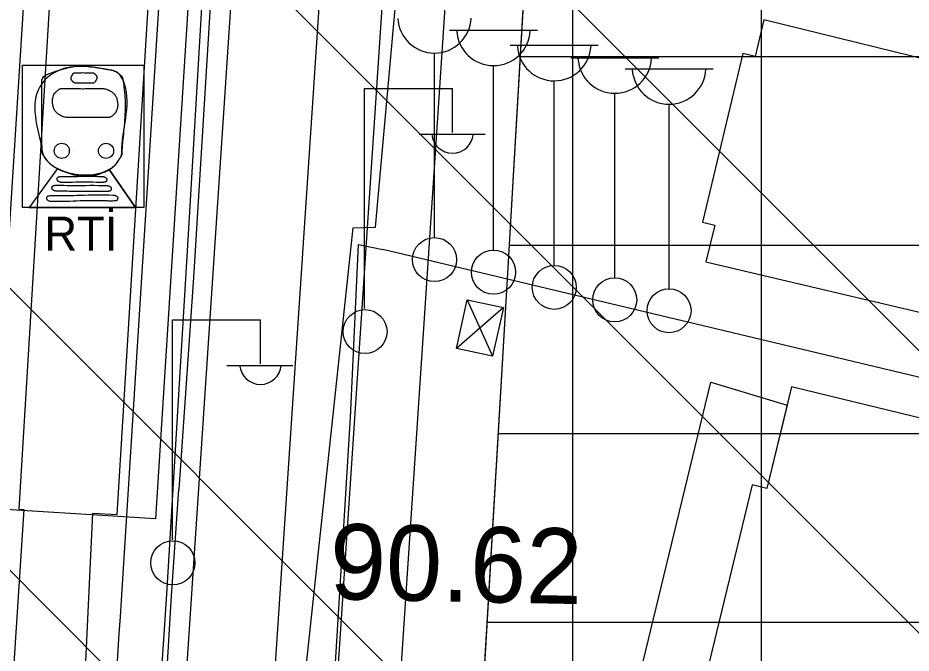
# Model space of a CAD drawing. Extents: x 417995 to 421451, y 4454518 to 4458015.
# Drawn here: x 420306.6 to 420377.6, y 4456593.7 to 4456644.2 of the extents above; entities that cross this region are included whole.
import ezdxf

# ---------------------------------------------------------------- set-up
doc = ezdxf.new("R2010")
doc.units = 0
for name, color, linetype in [('ADAKENARI', 7, 'Continuous'), ('B_Imalat', 7, 'Continuous'), ('B_Ins_Halinde', 7, 'Continuous'), ('B_Sundurma', 7, 'Continuous'), ('KALDIRIM_FAT', 7, 'Continuous'), ('LJ_SEMBOL', 7, 'Continuous'), ('PL_RAY_ISTASYON', 7, 'Continuous'), ('PL_RAYLI_TOPLU_TAŞIMA_İST', 7, 'Continuous'), ('PL_TİCARET', 7, 'Continuous'), ('RAYLI_TOPLU_TAŞIMA_HATTI', 7, 'Continuous'), ('S_Cad_Sok_Lambasi', 7, 'Continuous'), ('S_Elektrik_Diregi', 7, 'Continuous'), ('Sinir_Duvar_tek_tarafa_ait', 7, 'Continuous'), ('Sinir_Ist_Duvari', 7, 'Continuous'), ('SN_TR_SIVILASMA', 7, 'Continuous'), ('TRFAT_TİCARET', 7, 'Continuous'), ('Y_Kot_Noktasi', 7, 'Continuous'), ('Yol_Sose', 7, 'Continuous')]:
    doc.layers.add(name, color=color, linetype=linetype)

msp = doc.modelspace()

# ---------------------------------------------------------------- linework, layer by layer
at = {"layer": 'ADAKENARI'}
for p, q in [((420345.548, 4456624.341), (420347.312, 4456654.323)), ((420342.628, 4456574.693), (420345.548, 4456624.341))]:
    msp.add_line(p, q, dxfattribs=at)
at = {"layer": 'B_Imalat'}
msp.add_lwpolyline([(420388.142, 4456638.59), (420365.892, 4456644.052), (420365.209, 4456641.131), (420364.22, 4456641.368), (420361.019, 4456627.951), (420361.992, 4456627.718), (420361.292, 4456624.801), (420383.352, 4456619.614), (420384.566, 4456624.442), (420384.724, 4456624.389), (420386.982, 4456633.686)], close=True, dxfattribs=at)
at = {"layer": 'B_Ins_Halinde'}
for points in [[(420318.123, 4456664.608), (420315.622, 4456664.738), (420315.747, 4456667.522), (420312.826, 4456667.633), (420312.72, 4456665.065), (420310.259, 4456665.167), (420306.623, 4456605.135), (420307.028, 4456605.1), (420305.849, 4456587.154), (420311.662, 4456586.825), (420312.516, 4456604.804), (420314.463, 4456604.712)], [(420398.93, 4456606.339), (420403.896, 4456605.028), (420395.231, 4456569.269), (420352.988, 4456579.324), (420361.683, 4456615.244), (420367.747, 4456613.415), (420366.134, 4456606.778), (420364.969, 4456607.061), (420361.326, 4456592.074), (420386.941, 4456585.848), (420387.211, 4456586.956), (420392.806, 4456585.596), (420394.723, 4456593.481), (420395.745, 4456593.233)], [(420368.1, 4456614.868), (420366.134, 4456606.778), (420364.969, 4456607.061), (420361.326, 4456592.074), (420386.941, 4456585.848), (420387.211, 4456586.956), (420392.806, 4456585.596), (420394.723, 4456593.481), (420395.745, 4456593.233), (420399.168, 4456607.316)]]:
    msp.add_lwpolyline(points, close=True, dxfattribs=at)
at = {"layer": 'B_Sundurma'}
for p, q in [((420345.194, 4456621.18), (420341.454, 4456617.91)), ((420342.284, 4456621.79), (420344.324, 4456617.29))]:
    msp.add_line(p, q, dxfattribs=at)
msp.add_lwpolyline([(420341.454, 4456617.91), (420342.284, 4456621.79), (420345.194, 4456621.18), (420344.324, 4456617.29)], close=True, dxfattribs=at)
at = {"layer": 'KALDIRIM_FAT'}
for p, q in [((420370.124, 4457345.917), (420299.038, 4456277.891)), ((420377.108, 4457345.448), (420312.526, 4456375.14)), ((420348.426, 4456763.935), (420332.307, 4456521.76)), ((420342.794, 4456754.609), (420327.461, 4456524.245))]:
    msp.add_line(p, q, dxfattribs=at)
at = {"layer": 'LJ_SEMBOL'}
for p, q in [((420309.699, 4456632.214), (420307.452, 4456629.116)), ((420309.699, 4456632.214), (420307.452, 4456629.116)), ((420313.826, 4456632.14), (420315.912, 4456629.116)), ((420315.912, 4456629.116), (420313.826, 4456632.14)), ((420307.452, 4456629.116), (420315.912, 4456629.116))]:
    msp.add_line(p, q, dxfattribs=at)
msp.add_lwpolyline([(420306.911, 4456640.439), (420316.564, 4456640.439), (420316.564, 4456629.116), (420306.911, 4456629.116)], close=True, dxfattribs=at)
for centre in [(420310.047, 4456633.628), (420310.047, 4456633.628), (420313.569, 4456633.628), (420313.569, 4456633.628)]:
    msp.add_circle(centre, 0.601, dxfattribs=at)
for points in [[(420308.45, 4456634.013), (420308.45, 4456638.969), (420309.853, 4456640.044), (420313.523, 4456640.133), (420314.597, 4456639.745), (420314.925, 4456639.238), (420314.836, 4456633.804), (420314.733, 4456633.142), (420314.616, 4456632.963), (420314.448, 4456632.699), (420313.702, 4456632.072), (420310.002, 4456632.072), (420309.226, 4456632.52), (420308.778, 4456632.968), (420308.469, 4456633.699), (420308.45, 4456634.013)], [(420311.938, 4456639.015), (420311.133, 4456639.018), (420311.109, 4456639.02), (420311.086, 4456639.024), (420311.042, 4456639.04), (420311.02, 4456639.052), (420310.999, 4456639.065), (420310.979, 4456639.079), (420310.96, 4456639.095), (420310.941, 4456639.113), (420310.923, 4456639.132), (420310.889, 4456639.171), (420310.857, 4456639.214), (420310.826, 4456639.257), (420310.808, 4456639.29), (420310.796, 4456639.326), (420310.788, 4456639.401), (420310.789, 4456639.42), (420310.792, 4456639.439), (420310.799, 4456639.476), (420310.811, 4456639.513), (420310.826, 4456639.547), (420310.849, 4456639.593), (420310.873, 4456639.642), (420310.899, 4456639.69), (420310.914, 4456639.713), (420310.928, 4456639.736), (420310.943, 4456639.756), (420310.959, 4456639.775), (420310.977, 4456639.792), (420310.996, 4456639.808), (420311.016, 4456639.82), (420311.037, 4456639.829), (420311.059, 4456639.835), (420311.082, 4456639.837), (420311.491, 4456639.837), (420311.681, 4456639.845)], [(420310.803, 4456639.301), (420310.796, 4456639.326), (420310.792, 4456639.345), (420310.789, 4456639.363), (420310.788, 4456639.401), (420310.789, 4456639.42), (420310.792, 4456639.439), (420310.799, 4456639.476), (420310.811, 4456639.513), (420310.826, 4456639.547), (420310.849, 4456639.593), (420310.873, 4456639.642), (420310.899, 4456639.69), (420310.914, 4456639.713), (420310.928, 4456639.736), (420310.943, 4456639.756), (420310.959, 4456639.775), (420310.977, 4456639.792), (420310.996, 4456639.808), (420311.016, 4456639.82), (420311.037, 4456639.829), (420311.059, 4456639.835), (420311.082, 4456639.837), (420311.184, 4456639.837), (420311.287, 4456639.836), (420311.389, 4456639.835), (420311.491, 4456639.837), (420311.681, 4456639.845)], [(420311.681, 4456639.845), (420312.496, 4456639.834), (420312.52, 4456639.833), (420312.543, 4456639.828), (420312.587, 4456639.812), (420312.609, 4456639.801), (420312.63, 4456639.788), (420312.65, 4456639.773), (420312.669, 4456639.757), (420312.688, 4456639.739), (420312.706, 4456639.72), (420312.74, 4456639.681), (420312.772, 4456639.639), (420312.803, 4456639.595), (420312.821, 4456639.562), (420312.833, 4456639.526), (420312.841, 4456639.451), (420312.84, 4456639.432), (420312.837, 4456639.414), (420312.83, 4456639.376), (420312.818, 4456639.34), (420312.803, 4456639.305), (420312.78, 4456639.259), (420312.756, 4456639.21), (420312.729, 4456639.163), (420312.715, 4456639.139), (420312.701, 4456639.116), (420312.686, 4456639.096), (420312.67, 4456639.077), (420312.652, 4456639.06), (420312.633, 4456639.044), (420312.613, 4456639.032), (420312.592, 4456639.023), (420312.57, 4456639.017), (420312.547, 4456639.015), (420312.138, 4456639.015), (420311.938, 4456639.015)], [(420311.681, 4456639.845), (420312.496, 4456639.834), (420312.52, 4456639.833), (420312.543, 4456639.828), (420312.587, 4456639.812), (420312.609, 4456639.801), (420312.63, 4456639.788), (420312.65, 4456639.773), (420312.669, 4456639.757), (420312.688, 4456639.739), (420312.706, 4456639.72), (420312.74, 4456639.681), (420312.772, 4456639.639), (420312.803, 4456639.595), (420312.821, 4456639.562), (420312.826, 4456639.551)], [(420311.938, 4456639.015), (420311.133, 4456639.018), (420311.109, 4456639.02), (420311.086, 4456639.024), (420311.042, 4456639.04), (420311.02, 4456639.052), (420310.999, 4456639.065), (420310.979, 4456639.079), (420310.96, 4456639.095), (420310.941, 4456639.113), (420310.923, 4456639.132), (420310.889, 4456639.171), (420310.857, 4456639.214), (420310.826, 4456639.257), (420310.808, 4456639.29), (420310.803, 4456639.301)], [(420312.826, 4456639.551), (420312.833, 4456639.526), (420312.837, 4456639.508), (420312.84, 4456639.489), (420312.841, 4456639.451), (420312.84, 4456639.432), (420312.837, 4456639.414), (420312.83, 4456639.376), (420312.818, 4456639.34), (420312.803, 4456639.305), (420312.78, 4456639.259), (420312.756, 4456639.21), (420312.729, 4456639.163), (420312.715, 4456639.139), (420312.701, 4456639.116), (420312.686, 4456639.096), (420312.67, 4456639.077), (420312.652, 4456639.06), (420312.633, 4456639.044), (420312.613, 4456639.032), (420312.592, 4456639.023), (420312.57, 4456639.017), (420312.547, 4456639.015), (420312.138, 4456639.015), (420311.938, 4456639.015)], [(420311.796, 4456636.287), (420310.482, 4456636.285), (420310.383, 4456636.292), (420310.286, 4456636.309), (420310.097, 4456636.37), (420309.915, 4456636.461), (420309.825, 4456636.516), (420309.737, 4456636.575), (420309.646, 4456636.651), (420309.565, 4456636.738), (420309.495, 4456636.837), (420309.465, 4456636.889), (420309.436, 4456636.945), (420309.387, 4456637.065), (420309.35, 4456637.187), (420309.325, 4456637.31), (420309.309, 4456637.434), (420309.303, 4456637.558), (420309.308, 4456637.684), (420309.327, 4456637.809), (420309.361, 4456637.933), (420309.428, 4456638.098), (420309.52, 4456638.248), (420309.557, 4456638.291), (420309.597, 4456638.332), (420309.647, 4456638.379), (420309.698, 4456638.424), (420309.753, 4456638.466), (420309.811, 4456638.506), (420309.93, 4456638.565), (420310.057, 4456638.589), (420310.29, 4456638.591), (420310.522, 4456638.59), (420310.987, 4456638.582), (420311.452, 4456638.574), (420311.685, 4456638.572), (420311.917, 4456638.573), (420312.006, 4456638.576)], [(420309.303, 4456637.607), (420309.308, 4456637.684), (420309.327, 4456637.809), (420309.361, 4456637.933), (420309.428, 4456638.098), (420309.52, 4456638.248), (420309.557, 4456638.291), (420309.597, 4456638.332), (420309.647, 4456638.379), (420309.698, 4456638.424), (420309.753, 4456638.466), (420309.811, 4456638.506), (420309.868, 4456638.539), (420309.899, 4456638.553), (420309.93, 4456638.565), (420309.993, 4456638.582), (420310.057, 4456638.589), (420310.29, 4456638.591), (420310.522, 4456638.59), (420310.987, 4456638.582), (420311.452, 4456638.574), (420311.685, 4456638.572), (420311.917, 4456638.573), (420312.006, 4456638.576)], [(420312.006, 4456638.576), (420313.319, 4456638.577), (420313.418, 4456638.57), (420313.515, 4456638.553), (420313.704, 4456638.492), (420313.887, 4456638.401), (420313.976, 4456638.347), (420314.064, 4456638.287), (420314.156, 4456638.212), (420314.236, 4456638.124), (420314.306, 4456638.026), (420314.337, 4456637.973), (420314.365, 4456637.918), (420314.415, 4456637.797), (420314.451, 4456637.675), (420314.477, 4456637.552), (420314.493, 4456637.429), (420314.499, 4456637.304), (420314.493, 4456637.179), (420314.475, 4456637.053), (420314.441, 4456636.929), (420314.374, 4456636.765), (420314.281, 4456636.615), (420314.244, 4456636.571), (420314.205, 4456636.53), (420314.155, 4456636.483), (420314.103, 4456636.439), (420314.049, 4456636.396), (420313.991, 4456636.357), (420313.871, 4456636.298), (420313.744, 4456636.274), (420313.512, 4456636.271), (420313.279, 4456636.272), (420312.814, 4456636.28), (420312.349, 4456636.289), (420312.117, 4456636.29), (420311.884, 4456636.289), (420311.796, 4456636.287)], [(420312.006, 4456638.576), (420313.319, 4456638.577), (420313.418, 4456638.57), (420313.515, 4456638.553), (420313.704, 4456638.492), (420313.751, 4456638.471), (420313.797, 4456638.449), (420313.887, 4456638.401), (420313.976, 4456638.347), (420314.064, 4456638.287), (420314.156, 4456638.212), (420314.236, 4456638.124), (420314.306, 4456638.026), (420314.337, 4456637.973), (420314.365, 4456637.918), (420314.415, 4456637.797), (420314.451, 4456637.675), (420314.477, 4456637.552), (420314.493, 4456637.429), (420314.499, 4456637.304), (420314.498, 4456637.255)], [(420311.796, 4456636.287), (420310.482, 4456636.285), (420310.383, 4456636.292), (420310.286, 4456636.309), (420310.097, 4456636.37), (420310.05, 4456636.391), (420310.004, 4456636.413), (420309.915, 4456636.461), (420309.825, 4456636.516), (420309.737, 4456636.575), (420309.646, 4456636.651), (420309.565, 4456636.738), (420309.495, 4456636.837), (420309.465, 4456636.889), (420309.436, 4456636.945), (420309.387, 4456637.065), (420309.35, 4456637.187), (420309.325, 4456637.31), (420309.309, 4456637.434), (420309.303, 4456637.558), (420309.303, 4456637.607)], [(420314.498, 4456637.255), (420314.493, 4456637.179), (420314.475, 4456637.053), (420314.441, 4456636.929), (420314.374, 4456636.765), (420314.281, 4456636.615), (420314.244, 4456636.571), (420314.205, 4456636.53), (420314.155, 4456636.483), (420314.103, 4456636.439), (420314.049, 4456636.396), (420313.991, 4456636.357), (420313.933, 4456636.324), (420313.903, 4456636.31), (420313.871, 4456636.298), (420313.808, 4456636.281), (420313.744, 4456636.274), (420313.512, 4456636.271), (420313.279, 4456636.272), (420312.814, 4456636.28), (420312.349, 4456636.289), (420312.117, 4456636.29), (420311.884, 4456636.289), (420311.796, 4456636.287)], [(420313.826, 4456632.14), (420313.702, 4456632.072), (420313.266, 4456631.89), (420312.808, 4456631.768), (420311.855, 4456631.685), (420310.9, 4456631.796), (420310.218, 4456631.989), (420310.002, 4456632.072), (420309.849, 4456632.139), (420309.699, 4456632.214)], [(420310.637, 4456631.12), (420310.064, 4456631.115), (420309.981, 4456631.12), (420309.899, 4456631.136), (420309.82, 4456631.168), (420309.78, 4456631.192), (420309.761, 4456631.206), (420309.741, 4456631.221), (420309.704, 4456631.261), (420309.681, 4456631.307), (420309.671, 4456631.355), (420309.671, 4456631.378), (420309.675, 4456631.399), (420309.689, 4456631.448), (420309.713, 4456631.498), (420309.747, 4456631.539), (420309.768, 4456631.553), (420309.791, 4456631.561), (420309.883, 4456631.575), (420309.975, 4456631.583), (420310.159, 4456631.589), (420310.343, 4456631.586), (420310.637, 4456631.588)], [(420310.637, 4456631.12), (420310.064, 4456631.115), (420309.981, 4456631.12), (420309.899, 4456631.136), (420309.82, 4456631.168), (420309.78, 4456631.192), (420309.761, 4456631.206), (420309.741, 4456631.221), (420309.704, 4456631.261), (420309.681, 4456631.307), (420309.671, 4456631.355), (420309.671, 4456631.378), (420309.675, 4456631.399), (420309.689, 4456631.448), (420309.713, 4456631.498), (420309.747, 4456631.539), (420309.768, 4456631.553), (420309.791, 4456631.561), (420309.883, 4456631.575), (420309.975, 4456631.583), (420310.159, 4456631.589), (420310.343, 4456631.586), (420310.637, 4456631.588)], [(420310.637, 4456631.588), (420313.239, 4456631.588), (420313.322, 4456631.583), (420313.404, 4456631.567), (420313.483, 4456631.535), (420313.523, 4456631.511), (420313.542, 4456631.497), (420313.562, 4456631.482), (420313.599, 4456631.442), (420313.622, 4456631.396), (420313.632, 4456631.349), (420313.632, 4456631.326), (420313.629, 4456631.304), (420313.614, 4456631.256), (420313.59, 4456631.206), (420313.556, 4456631.164), (420313.535, 4456631.15), (420313.512, 4456631.142), (420313.42, 4456631.129), (420313.328, 4456631.12), (420313.144, 4456631.115), (420312.96, 4456631.117), (420312.777, 4456631.12), (420310.637, 4456631.12)], [(420310.637, 4456631.588), (420313.239, 4456631.588), (420313.322, 4456631.583), (420313.404, 4456631.567), (420313.483, 4456631.535), (420313.523, 4456631.511), (420313.542, 4456631.497), (420313.562, 4456631.482), (420313.599, 4456631.442), (420313.622, 4456631.396), (420313.632, 4456631.349), (420313.632, 4456631.326), (420313.629, 4456631.304), (420313.614, 4456631.256), (420313.59, 4456631.206), (420313.556, 4456631.164), (420313.535, 4456631.15), (420313.512, 4456631.142), (420313.42, 4456631.129), (420313.328, 4456631.12), (420313.144, 4456631.115), (420312.96, 4456631.117), (420312.777, 4456631.12), (420310.637, 4456631.12)], [(420310.993, 4456630.401), (420309.656, 4456630.425), (420309.573, 4456630.429), (420309.491, 4456630.446), (420309.412, 4456630.478), (420309.373, 4456630.501), (420309.353, 4456630.515), (420309.333, 4456630.531), (420309.296, 4456630.571), (420309.273, 4456630.617), (420309.263, 4456630.664), (420309.263, 4456630.687), (420309.267, 4456630.709), (420309.281, 4456630.757), (420309.305, 4456630.807), (420309.339, 4456630.848), (420309.36, 4456630.862), (420309.383, 4456630.87), (420309.475, 4456630.884), (420309.567, 4456630.893), (420309.751, 4456630.898), (420309.935, 4456630.895), (420310.993, 4456630.869)], [(420310.993, 4456630.401), (420309.656, 4456630.425), (420309.573, 4456630.429), (420309.491, 4456630.446), (420309.412, 4456630.478), (420309.373, 4456630.501), (420309.353, 4456630.515), (420309.333, 4456630.531), (420309.296, 4456630.571), (420309.273, 4456630.617), (420309.263, 4456630.664), (420309.263, 4456630.687), (420309.267, 4456630.709), (420309.281, 4456630.757), (420309.305, 4456630.807), (420309.339, 4456630.848), (420309.36, 4456630.862), (420309.383, 4456630.87), (420309.475, 4456630.884), (420309.567, 4456630.893), (420309.751, 4456630.898), (420309.935, 4456630.895), (420310.993, 4456630.869)], [(420310.993, 4456630.869), (420313.595, 4456630.869), (420313.679, 4456630.864), (420313.76, 4456630.848), (420313.84, 4456630.815), (420313.879, 4456630.792), (420313.898, 4456630.778), (420313.918, 4456630.763), (420313.955, 4456630.723), (420313.978, 4456630.677), (420313.988, 4456630.629), (420313.988, 4456630.606), (420313.985, 4456630.585), (420313.97, 4456630.536), (420313.946, 4456630.486), (420313.912, 4456630.445), (420313.891, 4456630.431), (420313.868, 4456630.423), (420313.776, 4456630.409), (420313.684, 4456630.401), (420313.501, 4456630.395), (420313.317, 4456630.398), (420313.133, 4456630.401), (420310.993, 4456630.401)], [(420310.993, 4456630.869), (420313.595, 4456630.869), (420313.679, 4456630.864), (420313.76, 4456630.848), (420313.84, 4456630.815), (420313.879, 4456630.792), (420313.898, 4456630.778), (420313.918, 4456630.763), (420313.955, 4456630.723), (420313.978, 4456630.677), (420313.988, 4456630.629), (420313.988, 4456630.606), (420313.985, 4456630.585), (420313.97, 4456630.536), (420313.946, 4456630.486), (420313.912, 4456630.445), (420313.891, 4456630.431), (420313.868, 4456630.423), (420313.776, 4456630.409), (420313.684, 4456630.401), (420313.501, 4456630.395), (420313.317, 4456630.398), (420313.133, 4456630.401), (420310.993, 4456630.401)], [(420311.511, 4456629.639), (420309.246, 4456629.599), (420309.162, 4456629.604), (420309.081, 4456629.62), (420309.002, 4456629.652), (420308.962, 4456629.676), (420308.943, 4456629.69), (420308.923, 4456629.705), (420308.886, 4456629.745), (420308.863, 4456629.791), (420308.853, 4456629.839), (420308.853, 4456629.862), (420308.856, 4456629.883), (420308.871, 4456629.932), (420308.895, 4456629.982), (420308.929, 4456630.023), (420308.95, 4456630.037), (420308.973, 4456630.045), (420309.065, 4456630.059), (420309.157, 4456630.067), (420309.341, 4456630.073), (420309.524, 4456630.07), (420311.511, 4456630.107)], [(420311.511, 4456629.639), (420309.246, 4456629.599), (420309.162, 4456629.604), (420309.081, 4456629.62), (420309.002, 4456629.652), (420308.962, 4456629.676), (420308.943, 4456629.69), (420308.923, 4456629.705), (420308.886, 4456629.745), (420308.863, 4456629.791), (420308.853, 4456629.839), (420308.853, 4456629.862), (420308.856, 4456629.883), (420308.871, 4456629.932), (420308.895, 4456629.982), (420308.929, 4456630.023), (420308.95, 4456630.037), (420308.973, 4456630.045), (420309.065, 4456630.059), (420309.157, 4456630.067), (420309.341, 4456630.073), (420309.524, 4456630.07), (420311.511, 4456630.107)], [(420311.511, 4456630.107), (420314.113, 4456630.107), (420314.196, 4456630.102), (420314.278, 4456630.086), (420314.357, 4456630.054), (420314.397, 4456630.03), (420314.416, 4456630.016), (420314.436, 4456630.001), (420314.473, 4456629.961), (420314.496, 4456629.915), (420314.506, 4456629.867), (420314.506, 4456629.844), (420314.503, 4456629.823), (420314.488, 4456629.775), (420314.464, 4456629.725), (420314.43, 4456629.683), (420314.409, 4456629.669), (420314.386, 4456629.661), (420314.294, 4456629.648), (420314.202, 4456629.639), (420314.018, 4456629.633), (420313.835, 4456629.636), (420313.651, 4456629.639), (420311.511, 4456629.639)], [(420311.511, 4456630.107), (420314.113, 4456630.107), (420314.196, 4456630.102), (420314.278, 4456630.086), (420314.357, 4456630.054), (420314.397, 4456630.03), (420314.416, 4456630.016), (420314.436, 4456630.001), (420314.473, 4456629.961), (420314.496, 4456629.915), (420314.506, 4456629.867), (420314.506, 4456629.844), (420314.503, 4456629.823), (420314.488, 4456629.775), (420314.464, 4456629.725), (420314.43, 4456629.683), (420314.409, 4456629.669), (420314.386, 4456629.661), (420314.294, 4456629.648), (420314.202, 4456629.639), (420314.018, 4456629.633), (420313.835, 4456629.636), (420313.651, 4456629.639), (420311.511, 4456629.639)]]:
    msp.add_spline(points, degree=3, dxfattribs=at)
msp.add_open_spline([(420308.45, 4456634.013), (420308.456, 4456633.908), (420308.462, 4456633.804), (420308.469, 4456633.699), (420308.484, 4456633.435), (420308.619, 4456633.196), (420308.778, 4456632.968), (420308.906, 4456632.786), (420309.053, 4456632.656), (420309.226, 4456632.52), (420309.47, 4456632.328), (420309.727, 4456632.185), (420310.002, 4456632.072), (420311.137, 4456631.606), (420312.576, 4456631.505), (420313.702, 4456632.072), (420313.998, 4456632.222), (420314.27, 4456632.426), (420314.448, 4456632.699), (420314.505, 4456632.787), (420314.56, 4456632.876), (420314.616, 4456632.963), (420314.655, 4456633.023), (420314.696, 4456633.078), (420314.733, 4456633.142), (420314.849, 4456633.341), (420314.814, 4456633.582), (420314.836, 4456633.804), (420315.01, 4456635.604), (420315.154, 4456637.433), (420314.925, 4456639.238), (420314.9, 4456639.438), (420314.779, 4456639.607), (420314.597, 4456639.745), (420314.253, 4456640.007), (420313.896, 4456640.068), (420313.523, 4456640.133), (420312.324, 4456640.344), (420311.058, 4456640.418), (420309.853, 4456640.044), (420309.272, 4456639.864), (420308.45, 4456639.558), (420308.45, 4456638.969), (420308.45, 4456637.317), (420308.45, 4456635.665), (420308.45, 4456634.013)], degree=3, dxfattribs=at)
at = {"layer": 'PL_RAY_ISTASYON'}
msp.add_line((420310.968, 4456633.592), (420310.968, 4456633.592), dxfattribs=at)
at = {"layer": 'PL_RAYLI_TOPLU_TAŞIMA_İST'}
msp.add_lwpolyline([(420305.969, 4456665.203), (420321.299, 4456664.232), (420317.506, 4456604.352), (420302.177, 4456605.323)], close=True, dxfattribs=at)
at = {"layer": 'PL_TİCARET'}
msp.add_lwpolyline([(420468.053, 4456636.5), (420431.205, 4456651.813), (420426.462, 4456653.784), (420424.604, 4456635.718), (420427.165, 4456635.102), (420424.095, 4456605.249), (420411.693, 4456608.262), (420409.33, 4456608.837), (420406.81, 4456561.362), (420362.271, 4456570.646), (420354.569, 4456572.251), (420342.628, 4456574.693), (420345.548, 4456624.341), (420347.312, 4456654.323), (420349.591, 4456693.075)], dxfattribs=at)
at = {"layer": 'RAYLI_TOPLU_TAŞIMA_HATTI'}
for p, q in [((420304.176, 4456600.5), (420311.393, 4456714.449)), ((420314.792, 4456597.891), (420322.132, 4456713.769))]:
    msp.add_line(p, q, dxfattribs=at)
msp.add_arc((419216.992, 4456667.427), 1100, 354.160759, 356.375611, dxfattribs=at)
at = {"layer": 'S_Cad_Sok_Lambasi'}
for p, q in [((420340.894, 4456643.23), (420347.894, 4456643.23)), ((420345.724, 4456642.02), (420352.724, 4456642.02)), ((420339.694, 4456626.73), (420339.694, 4456641.405)), ((420350.534, 4456641.03), (420357.534, 4456641.03)), ((420344.394, 4456625.73), (420344.394, 4456640.405)), ((420354.854, 4456640.16), (420361.854, 4456640.16)), ((420349.224, 4456624.52), (420349.224, 4456639.195)), ((420354.034, 4456623.53), (420354.034, 4456638.205)), ((420358.354, 4456622.66), (420358.354, 4456637.335))]:
    msp.add_line(p, q, dxfattribs=at)
for centre in [(420339.694, 4456624.98), (420344.394, 4456623.98), (420349.224, 4456622.77), (420354.034, 4456621.78), (420358.354, 4456620.91)]:
    msp.add_circle(centre, 1.75, dxfattribs=at)
for centre in [(420339.694, 4456644.334), (420344.394, 4456643.334), (420349.224, 4456642.124), (420354.034, 4456641.134), (420358.354, 4456640.264)]:
    msp.add_arc(centre, 2.929, 183.298, 356.90719, dxfattribs=at)
at = {"layer": 'S_Elektrik_Diregi'}
for p, q in [((420334.135, 4456621.087), (420334.135, 4456638.587)), ((420334.135, 4456638.587), (420341.135, 4456638.587)), ((420341.135, 4456635.087), (420341.135, 4456638.587)), ((420338.475, 4456634.947), (420343.725, 4456634.947)), ((420318.849, 4456602.7), (420318.849, 4456620.2)), ((420318.849, 4456620.2), (420325.849, 4456620.2)), ((420325.849, 4456616.7), (420325.849, 4456620.2)), ((420323.189, 4456616.56), (420328.439, 4456616.56))]:
    msp.add_line(p, q, dxfattribs=at)
for centre in [(420334.171, 4456619.252), (420318.885, 4456600.864)]:
    msp.add_circle(centre, 1.75, dxfattribs=at)
for centre in [(420341.136, 4456635.1), (420325.85, 4456616.713)]:
    msp.add_arc(centre, 1.658, 184.83843, 355.14641, dxfattribs=at)
at = {"layer": 'Sinir_Duvar_tek_tarafa_ait'}
for points in [[(420323.146, 4456678.942), (420320.189, 4456628.339), (420318.386, 4456598.362), (420317.33, 4456582.497)], [(420331.095, 4456579.812), (420331.384, 4456585.57), (420331.984, 4456595.51), (420333.014, 4456612.41), (420333.654, 4456626.19), (420335.599, 4456625.775)]]:
    msp.add_lwpolyline(points, dxfattribs=at)
at = {"layer": 'Sinir_Ist_Duvari'}
msp.add_lwpolyline([(420409.243, 4456608.241), (420335.599, 4456625.775)], dxfattribs=at)
at = {"layer": 'SN_TR_SIVILASMA'}
for p, q in [((421273.944, 4455722.028), (420248.837, 4456747.135)), ((421273.713, 4455699.809), (420266.798, 4456706.724)), ((421273.249, 4455655.372), (420276.011, 4456652.61)), ((421273.018, 4455633.153), (420276.278, 4456629.892))]:
    msp.add_line(p, q, dxfattribs=at)
at = {"layer": 'TRFAT_TİCARET'}
for p, q in [((420365.715, 4456569.928), (420365.715, 4456766.326)), ((420350.715, 4456573.039), (420350.715, 4456712.167)), ((420346.536, 4456641.136), (420425.161, 4456641.136)), ((420345.653, 4456626.136), (420426.243, 4456626.136)), ((420344.771, 4456611.136), (420424.7, 4456611.136)), ((420343.889, 4456596.136), (420408.656, 4456596.136))]:
    msp.add_line(p, q, dxfattribs=at)
at = {"layer": 'Yol_Sose'}
for points in [[(420327.414, 4456799.591), (420326.651, 4456782.597), (420325.848, 4456762.131), (420325.477, 4456743.519), (420325.001, 4456727.834), (420324.436, 4456706.627), (420324.736, 4456691.862), (420323.814, 4456672.956), (420322.435, 4456654.629), (420320.531, 4456623.542), (420319.355, 4456606.694)], [(420326.334, 4456539.92), (420329.533, 4456593.079), (420333.214, 4456627.497), (420335.003, 4456627.57), (420337.945, 4456660.269), (420340.101, 4456694.876)], [(420315.326, 4456540.542), (420318.779, 4456598.244), (420319.355, 4456606.694)]]:
    msp.add_lwpolyline(points, dxfattribs=at)

# ---------------------------------------------------------------- texts
at = {"layer": 'LJ_SEMBOL'}
msp.add_text('RTİ', height=2.7, dxfattribs=at).set_placement((420308.659, 4456625.699))
at = {"layer": 'Y_Kot_Noktasi'}
msp.add_text('90.62', height=6, rotation=358.82891, dxfattribs=at).set_placement((420331.323, 4456597.984))

doc.saveas('drawing.dxf')
